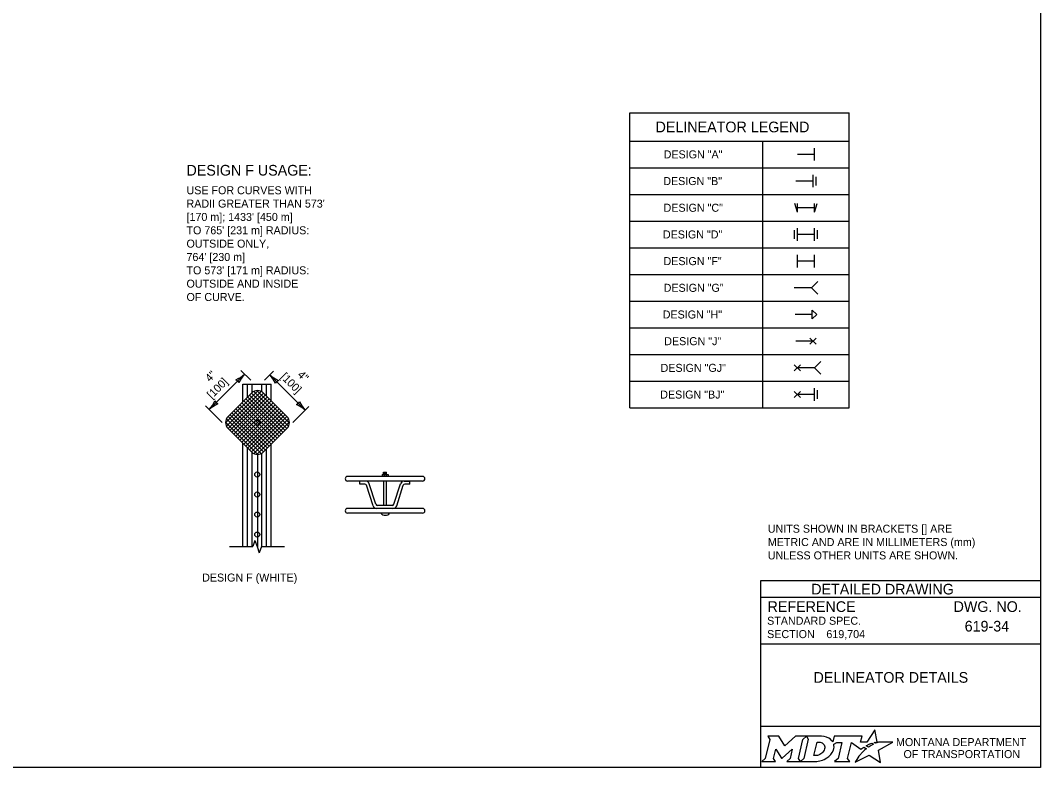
# Model space of a CAD drawing. Extents: x 49991.4 to 50021, y 49987.6 to 50011.4.
# Drawn here: x 50009.1 to 50016.75, y 49987.8 to 49993.4 of the extents above; entities that cross this region are included whole.
import ezdxf

# ---------------------------------------------------------------- set-up
doc = ezdxf.new("R2010")
doc.units = 0
for name, color, linetype in [('Default', 7, 'Continuous'), ('Level 1', 7, 'Continuous'), ('Level 2', 7, 'Continuous'), ('Level 3', 7, 'Continuous'), ('Level 5', 7, 'Continuous'), ('Level 6', 7, 'Continuous')]:
    doc.layers.add(name, color=color, linetype=linetype)

msp = doc.modelspace()

# ---------------------------------------------------------------- linework, layer by layer
at = {"layer": 'Default'}
for points in [[(50015.5126, 49987.9811), (50015.5023, 49987.9867), (50015.5139, 49987.9895), (50015.5255, 49987.9915), (50015.5081, 49988.0816), (50015.4486, 49987.9903), (50015.4013, 49987.9896), (50015.4116, 49988.0337), (50015.2024, 49988.0338), (50015.1923, 49987.9913), (50015.1865, 49987.9996)], [(50014.7056, 49988.0338), (50014.7197, 49988.0104), (50014.6862, 49987.8671), (50014.6605, 49987.8446), (50014.7621, 49987.8446), (50014.7486, 49987.8674), (50014.7648, 49987.9375), (50014.8085, 49987.8685), (50014.8138, 49987.8685), (50014.8889, 49987.938), (50014.8725, 49987.8669), (50014.8478, 49987.8449), (50014.9494, 49987.8449), (50014.9356, 49987.8682), (50014.9688, 49988.0106)], [(50014.9688, 49988.0106), (50014.9941, 49988.0338), (50014.9117, 49988.0338), (50014.8321, 49987.9608), (50014.7876, 49988.0335), (50014.7056, 49988.0338)], [(50015.1077, 49988.0338), (50014.9941, 49988.0338), (50015.0088, 49988.0109), (50014.9749, 49987.8671), (50014.9494, 49987.8449), (50015.06, 49987.8449)], [(50015.1317, 49987.9471), (50015.1305, 49987.939), (50015.1273, 49987.9297), (50015.1231, 49987.9215), (50015.1175, 49987.914), (50015.111, 49987.9071), (50015.1031, 49987.9008), (50015.0948, 49987.8961), (50015.0857, 49987.8922), (50015.0766, 49987.8899), (50015.0674, 49987.889), (50015.0515, 49987.889), (50015.0751, 49987.989), (50015.0911, 49987.989), (50015.0987, 49987.9884), (50015.1063, 49987.9865), (50015.1129, 49987.9835), (50015.119, 49987.9793), (50015.1238, 49987.9743), (50015.1275, 49987.9683), (50015.1302, 49987.9621), (50015.1318, 49987.9547), (50015.1318, 49987.9517), (50015.1317, 49987.9471)], [(50015.1991, 49987.9747), (50015.2237, 49987.9878), (50015.2606, 49987.9878), (50015.232, 49987.8673), (50015.2045, 49987.8446), (50015.3207, 49987.8446), (50015.3037, 49987.8675), (50015.3319, 49987.9877), (50015.4032, 49987.936), (50015.4243, 49987.9511), (50015.444, 49987.9402)], [(50015.3882, 49987.8843), (50015.3729, 49987.8599), (50015.3682, 49987.8524), (50015.3624, 49987.8438), (50015.3601, 49987.8395), (50015.4654, 49987.8926), (50015.5493, 49987.8375), (50015.5362, 49987.9302), (50015.6431, 49987.9886), (50015.5938, 49987.9894), (50015.5637, 49987.9898), (50015.5429, 49987.9901), (50015.5361, 49987.9886), (50015.5312, 49987.9874), (50015.5228, 49987.9851), (50015.5126, 49987.9811)], [(50015.4622, 49987.9535), (50015.4598, 49987.9518), (50015.4415, 49987.9614), (50015.4518, 49987.9671), (50015.4559, 49987.9693), (50015.4645, 49987.9733), (50015.4702, 49987.9759), (50015.4781, 49987.9789), (50015.4854, 49987.9816), (50015.4972, 49987.9742), (50015.4932, 49987.9721), (50015.4886, 49987.9696), (50015.4844, 49987.9674), (50015.4794, 49987.9645), (50015.4775, 49987.9634), (50015.4748, 49987.9618), (50015.4723, 49987.9604), (50015.47, 49987.9588), (50015.4674, 49987.957), (50015.4647, 49987.9552), (50015.4622, 49987.9535)], [(50015.4021, 49987.9004), (50015.4021, 49987.9004)], [(50015.1057, 49987.8522), (50015.1141, 49987.8548), (50015.1271, 49987.8602), (50015.1475, 49987.8712)]]:
    msp.add_lwpolyline(points, dxfattribs=at)
for centre, radius, start, end in [((50015.1308, 49987.9554), 0.0709, 339.53292, 15.85821), ((50015.0868, 49987.9727), 0.1183, 300.91025, 339.13831)]:
    msp.add_arc(centre, radius, start, end, dxfattribs=at)
for centre, major_axis, ratio, start_param, end_param in [((50015.1056, 49987.9864), (0.0834, -0.0037), 0.568097, 0.61298, 1.570796), ((50015.1612, 49987.9937), (0.0361, -0.0295), 0.469099, 1.225588, 1.570796), ((50015.3952, 49987.8923), (-0.00694, -0.00806), 0.008222, 0, 3.137361), ((50015.4119, 49987.9106), (-0.0098, -0.0102), 0.016458, 3.141593, 6.279097), ((50015.4329, 49987.9305), (-0.0112, -0.0097), 0.021651, 3.157348, 6.283185), ((50015.0603, 49987.9932), (0, 0.1484), 0.987302, 3.139398, 3.456847)]:
    msp.add_ellipse(centre, major_axis=major_axis, ratio=ratio, start_param=start_param, end_param=end_param, dxfattribs=at)
at = {"layer": 'Level 1'}
for p, q in [((50010.7703, 49990.6734), (50010.9829, 49990.6734)), ((50010.7703, 49990.5406), (50010.7703, 49990.6734)), ((50010.8058, 49990.5761), (50010.8058, 49990.6734)), ((50010.8412, 49990.6109), (50010.8412, 49990.6734)), ((50010.9121, 49990.6158), (50010.9121, 49990.6734)), ((50010.9476, 49990.5831), (50010.9476, 49990.6734)), ((50010.9829, 49990.5478), (50010.9829, 49990.6734)), ((50010.641, 49990.3817), (50010.8838, 49990.6245)), ((50010.647, 49990.3584), (50010.9071, 49990.6185)), ((50010.6591, 49990.3412), (50010.9244, 49990.6063)), ((50010.836, 49990.6063), (50010.6592, 49990.4295)), ((50010.6738, 49990.3265), (50010.9391, 49990.5916)), ((50010.6886, 49990.3117), (50010.9538, 49990.5769)), ((50010.8062, 49990.5766), (50011.0715, 49990.3115)), ((50010.8209, 49990.5913), (50011.0862, 49990.3262)), ((50010.8356, 49990.606), (50011.1009, 49990.3409)), ((50010.8528, 49990.6183), (50011.1131, 49990.358)), ((50010.8761, 49990.6245), (50011.1193, 49990.3812)), ((50011.1011, 49990.4295), (50010.9243, 49990.6063)), ((50010.7033, 49990.297), (50010.9685, 49990.5622)), ((50010.718, 49990.2823), (50010.9832, 49990.5475)), ((50010.7327, 49990.2676), (50010.9979, 49990.5328)), ((50010.7327, 49990.5031), (50010.9979, 49990.2379)), ((50010.7474, 49990.2529), (50011.0126, 49990.5181)), ((50010.7474, 49990.5178), (50011.0126, 49990.2526)), ((50010.7621, 49990.5325), (50011.0273, 49990.2673)), ((50010.7621, 49990.2382), (50011.0273, 49990.5034)), ((50010.7768, 49990.5472), (50011.042, 49990.282)), ((50010.7915, 49990.5619), (50011.0568, 49990.2968)), ((50010.6591, 49990.4295), (50010.9244, 49990.1644)), ((50010.6739, 49990.4442), (50010.9391, 49990.1791)), ((50010.6886, 49990.4589), (50010.9538, 49990.1938)), ((50010.7033, 49990.4736), (50010.9685, 49990.2085)), ((50010.718, 49990.4884), (50010.9832, 49990.2232)), ((50010.7768, 49990.2235), (50011.042, 49990.4887)), ((50010.7915, 49990.2088), (50011.0567, 49990.4739)), ((50010.8062, 49990.1941), (50011.0715, 49990.4592)), ((50010.8209, 49990.1794), (50011.0862, 49990.4445)), ((50010.8356, 49990.1647), (50011.1009, 49990.4298)), ((50010.641, 49990.3888), (50010.8837, 49990.1461)), ((50010.647, 49990.4122), (50010.9071, 49990.1522)), ((50010.8528, 49990.1523), (50011.1131, 49990.4127)), ((50010.8761, 49990.1462), (50011.1193, 49990.3894)), ((50010.6592, 49990.3411), (50010.836, 49990.1643)), ((50010.9243, 49990.1643), (50011.1011, 49990.3411)), ((50010.7703, 49989.4548), (50010.7703, 49990.23)), ((50010.8058, 49989.4548), (50010.8058, 49990.1945)), ((50010.9829, 49989.4548), (50010.9829, 49990.2229)), ((50010.8412, 49989.4548), (50010.8412, 49990.1597)), ((50010.9121, 49989.4548), (50010.9121, 49990.1548)), ((50010.9476, 49989.4548), (50010.9476, 49990.1876)), ((50012.1176, 49989.9813), (50011.5551, 49989.9813)), ((50011.8148, 49989.9946), (50011.8592, 49989.9946)), ((50011.8148, 49989.9946), (50011.8148, 49989.9813)), ((50011.8236, 49990.013), (50011.848, 49990.013)), ((50011.8236, 49989.9946), (50011.8236, 49990.013)), ((50011.8236, 49990.004), (50011.848, 49990.004)), ((50011.8286, 49990.0083), (50011.8447, 49990.0083)), ((50011.8286, 49989.9996), (50011.8447, 49989.9996)), ((50011.8286, 49989.9946), (50011.8286, 49989.9813)), ((50011.8447, 49989.9946), (50011.8447, 49989.9813)), ((50011.848, 49989.9946), (50011.848, 49990.013)), ((50011.8592, 49989.9946), (50011.8592, 49989.9813)), ((50012.1176, 49989.9461), (50011.5551, 49989.9461)), ((50011.6472, 49989.9226), (50011.6472, 49989.9461)), ((50011.6899, 49989.9461), (50011.6472, 49989.9461)), ((50011.6855, 49989.9226), (50011.6472, 49989.9226)), ((50011.7462, 49989.7612), (50011.6967, 49989.9144)), ((50011.7672, 49989.7725), (50011.7176, 49989.9258)), ((50011.8266, 49989.7644), (50011.8266, 49989.9461)), ((50011.8461, 49989.7644), (50011.8461, 49989.9461)), ((50011.9023, 49989.7725), (50011.9517, 49989.9258)), ((50011.9233, 49989.7612), (50011.9727, 49989.9144)), ((50011.9796, 49989.9461), (50012.0223, 49989.9461)), ((50012.0223, 49989.9226), (50011.9839, 49989.9226)), ((50012.0223, 49989.9226), (50012.0223, 49989.9461)), ((50012.1176, 49989.7409), (50011.5551, 49989.7409)), ((50011.8911, 49989.7644), (50011.7784, 49989.7644)), ((50012.1176, 49989.7057), (50011.5551, 49989.7057))]:
    msp.add_line(p, q, dxfattribs=at)
msp.add_lwpolyline([(49999.3835, 49998.9992), (50016.7501, 49998.9992), (50016.7501, 49987.7988), (49999.3835, 49987.7988)], close=True, dxfattribs=at)
for centre in [(50010.8777, 49990.3851), (50010.878, 49989.9956), (50010.8781, 49989.8456), (50010.878, 49989.6956), (50010.8781, 49989.5455)]:
    msp.add_circle(centre, 0.0188, dxfattribs=at)
for centre, radius, start, end in [((50010.8801, 49990.5621), 0.0625, 45, 135), ((50010.7034, 49990.3853), 0.0625, 135, 225), ((50011.0569, 49990.3853), 0.0625, 315, 45), ((50010.8801, 49990.2085), 0.0625, 225, 315), ((50011.5551, 49989.9637), 0.0176, 90, 270), ((50012.1176, 49989.9637), 0.0176, 270, 90), ((50011.6855, 49989.9108), 0.0117, 17.88906, 90), ((50011.6898, 49989.9168), 0.0293, 17.88804, 90), ((50011.9795, 49989.9168), 0.0293, 90, 162.11105), ((50011.9839, 49989.9108), 0.0117, 90, 162.11094), ((50011.5551, 49989.7233), 0.0176, 90, 270), ((50011.774, 49989.7701), 0.0293, 197.88906, 270), ((50011.7784, 49989.7761), 0.0117, 197.88895, 270), ((50011.8911, 49989.7761), 0.0117, 270, 342.11105), ((50011.8954, 49989.7701), 0.0293, 270, 342.11094), ((50012.1176, 49989.7233), 0.0176, 270, 90), ((50011.8378, 49989.7328), 0.0425, 219.66345, 320.33655)]:
    msp.add_arc(centre, radius, start, end, dxfattribs=at)
at = {"layer": 'Level 2'}
for p, q in [((50013.6708, 49992.7058), (50015.3163, 49992.7058)), ((50013.6708, 49991.6948), (50013.6708, 49992.7058)), ((50015.3163, 49991.6948), (50015.3163, 49992.7058)), ((50013.6708, 49992.4948), (50015.3163, 49992.4948)), ((50014.6672, 49991.6948), (50014.6672, 49992.4948)), ((50015.0562, 49992.3479), (50015.0562, 49992.4417)), ((50015.0562, 49992.3948), (50014.9273, 49992.3948)), ((50013.6708, 49992.2948), (50015.3163, 49992.2948)), ((50015.0452, 49992.1948), (50014.9163, 49992.1948)), ((50015.0452, 49992.1479), (50015.0452, 49992.2417)), ((50015.067, 49992.1621), (50015.067, 49992.2277)), ((50013.6708, 49992.0948), (50015.3163, 49992.0948)), ((50014.9272, 49991.962), (50014.9087, 49992.027)), ((50014.9272, 49991.962), (50014.9272, 49992.0276)), ((50015.0561, 49991.9948), (50014.9272, 49991.9948)), ((50015.0561, 49991.962), (50015.0561, 49992.0276)), ((50015.0561, 49991.962), (50015.0746, 49992.027)), ((50013.6708, 49991.8948), (50015.3163, 49991.8948)), ((50014.9058, 49991.7619), (50014.9058, 49991.8277)), ((50014.9273, 49991.7479), (50014.9273, 49991.8417)), ((50015.0561, 49991.7479), (50015.0561, 49991.8417)), ((50015.0776, 49991.7619), (50015.0776, 49991.8277)), ((50015.0561, 49991.7948), (50014.9273, 49991.7948)), ((50013.6708, 49991.6948), (50015.3163, 49991.6948)), ((50013.6708, 49990.4948), (50013.6708, 49991.6948)), ((50014.6672, 49990.4948), (50014.6672, 49991.6948)), ((50015.3163, 49990.4948), (50015.3163, 49991.6948)), ((50014.9273, 49991.5479), (50014.9273, 49991.6418)), ((50015.0562, 49991.5948), (50014.9273, 49991.5948)), ((50015.0562, 49991.5479), (50015.0562, 49991.6418)), ((50013.6708, 49991.4948), (50015.3163, 49991.4948)), ((50015.0796, 49991.4417), (50015.0327, 49991.3948)), ((50015.0327, 49991.3948), (50014.9038, 49991.3948)), ((50015.0796, 49991.348), (50015.0327, 49991.3948)), ((50013.6708, 49991.2948), (50015.3163, 49991.2948)), ((50015.0385, 49991.1948), (50014.9096, 49991.1948)), ((50015.0385, 49991.1621), (50015.0385, 49991.2277)), ((50015.0738, 49991.1948), (50015.0385, 49991.2277)), ((50015.0385, 49991.1621), (50015.0738, 49991.1948)), ((50013.6708, 49991.0948), (50015.3163, 49991.0948)), ((50015.0446, 49990.9948), (50014.9156, 49990.9948)), ((50015.0678, 49990.9716), (50015.0214, 49991.018)), ((50015.0678, 49991.018), (50015.0214, 49990.9716)), ((50013.6708, 49990.8948), (50015.3163, 49990.8948)), ((50014.9505, 49990.818), (50014.9041, 49990.7716)), ((50014.9505, 49990.7716), (50014.9041, 49990.818)), ((50015.1031, 49990.8417), (50015.0562, 49990.7948)), ((50015.0562, 49990.7948), (50014.9273, 49990.7948)), ((50015.1031, 49990.748), (50015.0562, 49990.7948)), ((50013.6708, 49990.6948), (50015.3163, 49990.6948)), ((50014.9505, 49990.618), (50014.9041, 49990.5716)), ((50014.9505, 49990.5716), (50014.9041, 49990.618)), ((50015.0562, 49990.5948), (50014.9273, 49990.5948)), ((50015.0562, 49990.5479), (50015.0562, 49990.6417)), ((50015.078, 49990.5621), (50015.078, 49990.6277)), ((50013.6708, 49990.4948), (50015.3163, 49990.4948))]:
    msp.add_line(p, q, dxfattribs=at)
at = {"layer": 'Level 3'}
for p, q in [((50010.518, 49990.4824), (50010.7832, 49990.7475)), ((50010.8291, 49990.7017), (50010.7549, 49990.7758)), ((50011.0007, 49990.771), (50010.9314, 49990.7017)), ((50010.9724, 49990.7427), (50011.2376, 49990.4776)), ((50010.4898, 49990.5107), (50010.615, 49990.3853)), ((50011.1453, 49990.3853), (50011.2659, 49990.5059))]:
    msp.add_line(p, q, dxfattribs=at)
for centre, radius, start, end in [((50010.6326, 49990.9111), 0.2223, 292.44521, 312.62871), ((50010.9558, 49990.591), 0.233, 137.81651, 157.06636), ((50010.8088, 49990.592), 0.2223, 22.46682, 42.65033), ((50011.1287, 49990.9154), 0.233, 227.83812, 247.08797), ((50010.6925, 49990.6568), 0.0548, 27.12801, 62.85037), ((50011.063, 49990.652), 0.0548, 117.14963, 152.87199), ((50010.3453, 49990.6389), 0.233, 317.81651, 337.06636), ((50010.6686, 49990.3188), 0.2223, 112.44521, 132.62871), ((50010.6087, 49990.573), 0.0548, 207.12801, 242.85038), ((50011.1469, 49990.5682), 0.0548, 297.14963, 332.87199), ((50011.0812, 49990.3048), 0.233, 47.83812, 67.08797), ((50011.4011, 49990.6282), 0.2223, 202.46682, 222.65032)]:
    msp.add_arc(centre, radius, start, end, dxfattribs=at)
at = {"layer": 'Level 5'}
for p, q in [((50010.8789, 49990.1461), (50010.8789, 49989.4483)), ((50016.7501, 49989.1988), (50014.6501, 49989.1988)), ((50014.6501, 49989.1988), (50014.6501, 49987.7988)), ((50016.7501, 49989.0738), (50014.6501, 49989.0738)), ((50016.3862, 49988.8587), (50016.3862, 49988.8587)), ((50015.1444, 49988.7993), (50015.1444, 49988.7993)), ((50016.7501, 49988.7238), (50014.6501, 49988.7238)), ((50015.7001, 49988.4747), (50015.7001, 49988.4747)), ((50016.7501, 49988.1057), (50014.6501, 49988.1057))]:
    msp.add_line(p, q, dxfattribs=at)
at = {"layer": 'Level 6'}
for p, q in [((50010.6703, 49989.4548), (50010.8442, 49989.4548)), ((50010.8604, 49989.5005), (50010.8442, 49989.4548)), ((50010.8604, 49989.5005), (50010.8766, 49989.4548)), ((50010.8766, 49989.4548), (50010.8928, 49989.4091)), ((50010.909, 49989.4548), (50010.8928, 49989.4091)), ((50010.909, 49989.4548), (50011.0829, 49989.4548))]:
    msp.add_line(p, q, dxfattribs=at)

# ---------------------------------------------------------------- texts
at = {"layer": 'Default'}
for s, p in [('MONTANA DEPARTMENT', (50015.6663, 49987.96)), ('OF TRANSPORTATION', (50015.7225, 49987.87))]:
    msp.add_text(s, height=0.06, dxfattribs=at).set_placement(p)
at = {"layer": 'Level 2'}
for s, height, p in [('DELINEATOR LEGEND', 0.08, (50013.8641, 49992.5603)), ('DESIGN "A"', 0.06, (50013.9247, 49992.3648)), ('DESIGN F USAGE:', 0.08, (50010.3479, 49992.2359)), ('DESIGN "B"', 0.06, (50013.9219, 49992.1648)), ('USE FOR CURVES WITH', 0.06, (50010.3479, 49992.0959)), ("RADII GREATER THAN 573' ", 0.06, (50010.3479, 49991.9959)), ("[170 m]; 1433' [450 m] ", 0.06, (50010.3479, 49991.8959)), ('DESIGN "C"', 0.06, (50013.9241, 49991.9648)), ("TO 765' [231 m] RADIUS:", 0.06, (50010.3479, 49991.7959)), ('DESIGN "D"', 0.06, (50013.9193, 49991.7648)), ('OUTSIDE ONLY,', 0.06, (50010.3479, 49991.6959)), ("764' [230 m]", 0.06, (50010.3479, 49991.5959)), ('DESIGN "F"', 0.06, (50013.9234, 49991.5648)), ("TO 573' [171 m] RADIUS:", 0.06, (50010.3479, 49991.4959)), ('OUTSIDE AND INSIDE ', 0.06, (50010.3479, 49991.3959)), ('DESIGN "G"', 0.06, (50013.9247, 49991.3648)), ('OF CURVE.', 0.06, (50010.3479, 49991.2959)), ('DESIGN "H"', 0.06, (50013.9176, 49991.1648)), ('DESIGN "J"', 0.06, (50013.9292, 49990.9648)), ('DESIGN "GJ"', 0.06, (50013.9017, 49990.7648)), ('DESIGN "BJ"', 0.06, (50013.8989, 49990.5648)), ('UNITS SHOWN IN BRACKETS [] ARE ', 0.06, (50014.7053, 49989.5592)), ('METRIC AND ARE IN MILLIMETERS (mm) ', 0.06, (50014.7053, 49989.4592)), ('UNLESS OTHER UNITS ARE SHOWN.', 0.06, (50014.7053, 49989.3592)), ('DESIGN F (WHITE)', 0.06, (50010.465, 49989.1931)), ('619-34', 0.08, (50016.1811, 49988.8187)), ('619,704', 0.06, (50015.1444, 49988.7693)), ('DELINEATOR DETAILS', 0.08, (50015.0482, 49988.4347))]:
    msp.add_text(s, height=height, dxfattribs=at).set_placement(p)
for s, rotation, p in [('4"', 45, (50010.523, 49990.6854)), ('[100]', 315, (50011.0483, 49990.7233)), ('4"', 315, (50011.1755, 49990.7376)), ('[100]', 45, (50010.5373, 49990.5582))]:
    msp.add_text(s, height=0.06, rotation=rotation, dxfattribs=at).set_placement(p)
at = {"layer": 'Level 5'}
for s, height, p in [('DETAILED DRAWING', 0.0799, (50015.0311, 49989.0963)), ('REFERENCE', 0.08, (50014.7037, 49988.9654)), ('DWG. NO.', 0.08, (50016.0979, 49988.9654)), ('STANDARD SPEC.', 0.06, (50014.7004, 49988.8694)), ('SECTION', 0.06, (50014.7004, 49988.7694))]:
    msp.add_text(s, height=height, dxfattribs=at).set_placement(p)

doc.saveas('drawing.dxf')
